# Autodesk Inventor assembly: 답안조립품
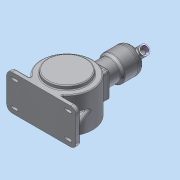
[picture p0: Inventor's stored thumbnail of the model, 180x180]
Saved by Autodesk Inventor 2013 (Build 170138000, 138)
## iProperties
Created: 2015-06
Part Number: 답안조립품
Document SubType Name: Assembly
Designer: dgall
Author: dgall
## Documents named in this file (15)
- C:\Documents and Settings\dgall\바탕 화면\450605V1010\답안조립품.iam
- C:\Documents and Settings\dgall\바탕 화면\450605V1010\1번본체.ipt
- C:\Documents and Settings\dgall\바탕 화면\450605V1010\실린더.ipt
- C:\Documents and Settings\dgall\바탕 화면\450605V1010\실린더헤드.ipt
- C:\Documents and Settings\dgall\바탕 화면\450605V1010\메인커버.ipt
- C:\Documents and Settings\dgall\바탕 화면\450605V1010\메인 크랭크 축-구동부.ipt
- C:\Documents and Settings\dgall\바탕 화면\450605V1010\크랭크 서브축.ipt
- C:\Documents and Settings\dgall\바탕 화면\450605V1010\커넥팅 로드.ipt
- C:\Documents and Settings\dgall\바탕 화면\450605V1010\피스톤.ipt
- C:\Documents and Settings\dgall\바탕 화면\450605V1010\피스톤 핀.ipt
- C:\Documents and Settings\dgall\바탕 화면\450605V1010\베어링 6204.ipt
- C:\Documents and Settings\dgall\바탕 화면\450605V1010\베어링 NA 4902.ipt
- C:\Documents and Settings\dgall\바탕 화면\450605V1010\오일실.ipt
- C:\Documents and Settings\dgall\바탕 화면\450605V1010\M5x0.8.ipt
- C:\Documents and Settings\dgall\바탕 화면\450605V1010\M4x0.7.ipt
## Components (15 placed, 5 different names)
1. 1번본체:1
2. 피스톤:1
3. 피스톤 핀:1
4. M5x0.8:1
5. M5x0.8:2
6. M5x0.8:3
7. M5x0.8:4
8. M4x0.7:1
9. M4x0.7:2
10. M4x0.7:3
11. M4x0.7:4
12. M4x0.7:5
13. M4x0.7:6
14. M4x0.7:7
15. M4x0.7:8
